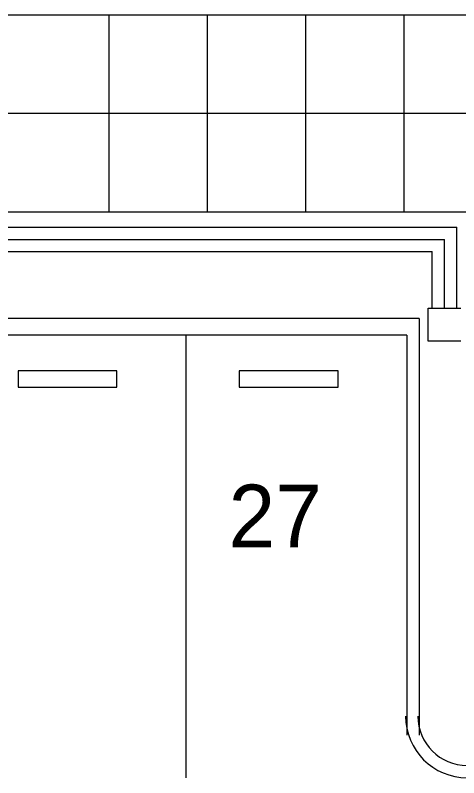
# Model space of a CAD drawing. Extents: x 6711323 to 6714641, y 1869258 to 1871224.
# Drawn here: x 6712851.17 to 6712869.21, y 1869710.07 to 1869741.07 of the extents above; entities that cross this region are included whole.
import ezdxf

# ---------------------------------------------------------------- set-up
doc = ezdxf.new("R2010")
doc.units = 0
for name, color, linetype in [('Curb Gutter (21)', 7, 'Continuous'), ('Front Align (17)', 7, 'Continuous'), ('Misc CnstDet(22)', 7, 'Continuous'), ('Pave Edges (20)', 7, 'Continuous'), ('Ramp Anno (14)', 7, 'Continuous'), ('Undefined (Lv19)', 7, 'Continuous'), ('Undefined (Lv26)', 7, 'Continuous')]:
    doc.layers.add(name, color=color, linetype=linetype)

msp = doc.modelspace()

# ---------------------------------------------------------------- linework, layer by layer
at = {"layer": 'Curb Gutter (21)'}
for p, q in [((6712867.607, 1869728.739), (6712657.363, 1869728.739)), ((6712867.607, 1869728.739), (6712867.607, 1869711.801)), ((6712867.107, 1869728.072), (6712835.472, 1869728.072)), ((6712867.107, 1869728.072), (6712867.107, 1869711.801))]:
    msp.add_line(p, q, dxfattribs=at)
for radius in [2.5, 2]:
    msp.add_arc((6712869.552, 1869712.572), radius, 180, 270, dxfattribs=at)
at = {"layer": 'Front Align (17)'}
msp.add_line((6712858.107, 1869728.072), (6712858.107, 1869710.072), dxfattribs=at)
for points in [[(6712855.302, 1869726.621), (6712851.287, 1869726.621), (6712851.287, 1869725.952), (6712855.302, 1869725.952)], [(6712864.302, 1869726.621), (6712860.287, 1869726.621), (6712860.287, 1869725.952), (6712864.302, 1869725.952)]]:
    msp.add_lwpolyline(points, close=True, dxfattribs=at)
at = {"layer": 'Misc CnstDet(22)'}
for p in [(6712600.99, 1869731.962), (6712868.629, 1869729.158)]:
    msp.add_line(p, (6712868.629, 1869731.962), dxfattribs=at)
at = {"layer": 'Pave Edges (20)'}
for p, q in [((6712858.974, 1869741.072), (6712858.974, 1869733.072)), ((6712866.974, 1869741.072), (6712866.974, 1869733.072)), ((6712939.639, 1869737.072), (6712560.557, 1869737.072))]:
    msp.add_line(p, q, dxfattribs=at)
at = {"layer": 'Undefined (Lv19)'}
for p, q in [((6712951.646, 1869741.072), (6712671.076, 1869741.072)), ((6712854.974, 1869741.072), (6712854.974, 1869733.072)), ((6712862.974, 1869741.072), (6712862.974, 1869733.072)), ((6712951.556, 1869733.072), (6712672.694, 1869733.072))]:
    msp.add_line(p, q, dxfattribs=at)
at = {"layer": 'Undefined (Lv26)'}
for p, q in [((6712600.99, 1869732.462), (6712869.129, 1869732.462)), ((6712869.129, 1869729.158), (6712869.129, 1869732.462)), ((6712600.99, 1869731.462), (6712868.129, 1869731.462)), ((6712868.129, 1869729.158), (6712868.129, 1869731.462)), ((6712867.962, 1869727.825), (6712867.962, 1869729.158)), ((6712867.962, 1869729.158), (6712869.296, 1869729.158)), ((6712869.296, 1869727.825), (6712867.962, 1869727.825))]:
    msp.add_line(p, q, dxfattribs=at)

# ---------------------------------------------------------------- texts
at = {"layer": 'Ramp Anno (14)'}
msp.add_text('27', height=2.55, dxfattribs=at).set_placement((6712859.85, 1869719.438))

doc.saveas('drawing.dxf')
